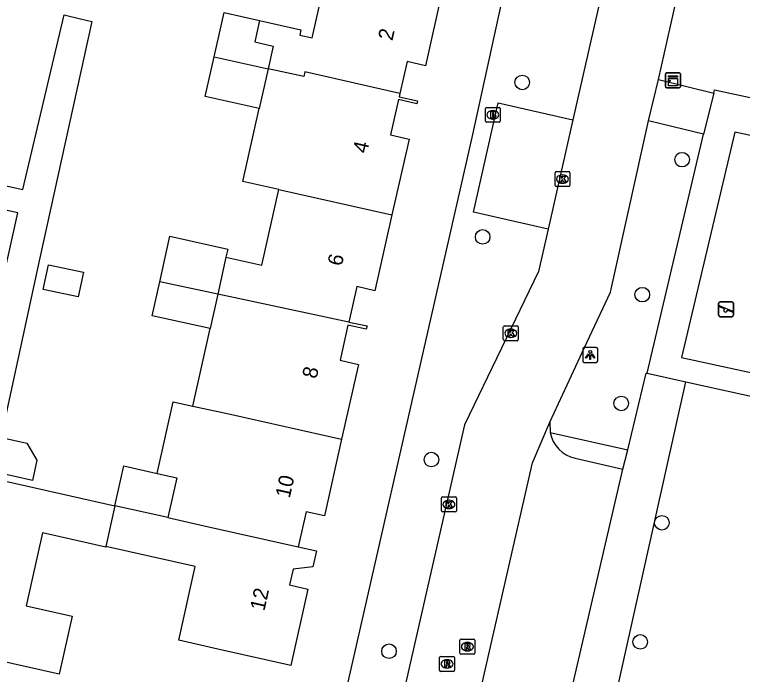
# Model space of a CAD drawing. Extents: x 163686 to 164493, y 382719 to 383870.
# Drawn here: x 164037.9 to 164086.64, y 383510.38 to 383554.53 of the extents above; entities that cross this region are included whole.
import ezdxf

# ---------------------------------------------------------------- set-up
doc = ezdxf.new("R2010")
doc.units = 0
for name, color, linetype in [('IMGEO_Boom', 7, 'Continuous'), ('IMGEO_Brandkraan', 7, 'Continuous'), ('IMGEO_Groenvoorziening', 7, 'Continuous'), ('IMGEO_Kast', 7, 'Continuous'), ('IMGEO_Kolk', 7, 'Continuous'), ('IMGEO_Lichtpunt', 7, 'Continuous'), ('IMGEO_Pand', 7, 'Continuous'), ('IMGEO_Pand_nummerreeks', 7, 'Continuous'), ('IMGEO_Parkeervlak_open', 7, 'Continuous'), ('IMGEO_Rijbaan_lokaal_open', 7, 'Continuous'), ('IMGEO_Rioolput', 7, 'Continuous'), ('IMGEO_Speelvoorziening', 7, 'Continuous'), ('IMGEO_Terreindeel_open', 7, 'Continuous'), ('IMGEO_Voetpad_open', 7, 'Continuous'), ('IMGEO_Woonerf_open', 7, 'Continuous')]:
    doc.layers.add(name, color=color, linetype=linetype)

msp = doc.modelspace()

# ---------------------------------------------------------------- linework, layer by layer
at = {"layer": 'IMGEO_Boom'}
for centre in [(164071.892, 383549.993), (164082.598, 383544.825), (164069.24, 383539.655), (164079.93, 383535.792), (164078.518, 383528.511), (164065.811, 383524.756), (164081.24, 383520.526), (164079.794, 383512.556), (164062.971, 383511.933)]:
    msp.add_circle(centre, 0.489, dxfattribs=at)
at = {"layer": 'IMGEO_Brandkraan'}
for p, q in [((164069.422, 383547.398), (164069.422, 383548.25)), ((164069.497, 383548.324), (164070.349, 383548.324)), ((164069.91, 383548.104), (164069.935, 383548.104)), ((164070.423, 383548.25), (164070.423, 383547.398)), ((164069.933, 383547.544), (164069.908, 383547.544)), ((164070.349, 383547.324), (164069.497, 383547.324))]:
    msp.add_line(p, q, dxfattribs=at)
for points in [[(164069.422, 383547.398), (164069.422, 383548.25)], [(164069.497, 383548.324), (164070.349, 383548.324)], [(164069.77, 383548.024), (164069.77, 383547.624), (164069.983, 383547.624)], [(164070.001, 383548.024), (164069.77, 383548.024)], [(164070.423, 383548.25), (164070.423, 383547.398)], [(164069.949, 383547.943), (164069.895, 383547.943), (164069.895, 383547.867)], [(164069.895, 383547.867), (164069.948, 383547.867)], [(164069.957, 383547.791), (164069.895, 383547.791), (164069.895, 383547.71)], [(164069.895, 383547.71), (164069.957, 383547.71)], [(164070.349, 383547.324), (164069.497, 383547.324)]]:
    msp.add_lwpolyline(points, dxfattribs=at)
for centre, radius, start, end in [((164069.499, 383548.248), 0.0765, 91.552, 178.448), ((164069.499, 383548.248), 0.0765, 91.552, 178.448), ((164070.005, 383547.879), 0.145, 59.4692, 91.5367), ((164070.03, 383547.926), 0.0922, 285.5137, 58.1501), ((164070.347, 383548.248), 0.0765, 1.552, 88.448), ((164070.347, 383548.248), 0.0765, 1.552, 88.448), ((164069.95, 383547.905), 0.0379, 267.8285, 90.9355), ((164069.958, 383547.75), 0.0404, 269.8759, 90.5077), ((164069.989, 383547.875), 0.251, 268.6676, 293.5347), ((164070.035, 383547.734), 0.105, 301.3115, 78.989), ((164069.499, 383547.4), 0.0765, 181.552, 268.448), ((164069.499, 383547.4), 0.0765, 181.552, 268.448), ((164070.347, 383547.4), 0.0765, 271.552, 358.448), ((164070.347, 383547.4), 0.0765, 271.552, 358.448)]:
    msp.add_arc(centre, radius, start, end, dxfattribs=at)
for centre, major_axis, ratio, start_param, end_param in [((164069.909, 383547.824), (-0.387, 0.002), 0.722429, 4.712389, 7.853982), ((164069.934, 383547.824), (-0.39, 0.002), 0.717154, 1.570796, 4.712389)]:
    msp.add_ellipse(centre, major_axis=major_axis, ratio=ratio, start_param=start_param, end_param=end_param, dxfattribs=at)
at = {"layer": 'IMGEO_Groenvoorziening'}
for points in [[(164084.714, 383549.273), (164084.769, 383549.493), (164114.437, 383543.108)], [(164080.248, 383530.541), (164084.032, 383546.541)], [(164078.964, 383525.408), (164080.184, 383530.549), (164080.248, 383530.541)], [(164080.248, 383530.541), (164082.853, 383529.966)], [(164068.968, 383467.759), (164082.853, 383529.966)], [(164082.853, 383529.966), (164127.033, 383520.232)]]:
    msp.add_lwpolyline(points, dxfattribs=at)
at = {"layer": 'IMGEO_Kast'}
for p, q in [((164081.483, 383549.714), (164081.483, 383550.555)), ((164081.483, 383550.555), (164081.483, 383549.714)), ((164081.558, 383550.639), (164082.399, 383550.639)), ((164082.399, 383550.639), (164081.558, 383550.639)), ((164082.483, 383550.564), (164082.483, 383549.723)), ((164082.483, 383549.723), (164082.483, 383550.564)), ((164082.408, 383549.639), (164081.567, 383549.639)), ((164081.567, 383549.639), (164082.408, 383549.639))]:
    msp.add_line(p, q, dxfattribs=at)
for points in [[(164081.678, 383550.429), (164082.278, 383550.429), (164082.278, 383550.344), (164081.678, 383550.344), (164081.678, 383550.429)], [(164081.678, 383550.254), (164082.278, 383550.254), (164082.278, 383549.765), (164081.678, 383549.765), (164081.678, 383550.254)]]:
    msp.add_lwpolyline(points, dxfattribs=at)
msp.add_circle((164081.762, 383550.103), 0.0377, dxfattribs=at)
for centre, start, end in [((164081.561, 383550.561), 92.4484, 184.2845), ((164081.561, 383550.561), 92.4484, 184.2845), ((164082.405, 383550.561), 2.4484, 94.2845), ((164082.405, 383550.561), 2.4484, 94.2845), ((164081.561, 383549.717), 182.4484, 274.2845), ((164081.561, 383549.717), 182.4484, 274.2845), ((164082.405, 383549.717), 272.4484, 4.2845), ((164082.405, 383549.717), 272.4484, 4.2845)]:
    msp.add_arc(centre, 0.0779, start, end, dxfattribs=at)
at = {"layer": 'IMGEO_Kolk'}
for p, q in [((164074.085, 383543.099), (164074.085, 383543.951)), ((164074.16, 383544.025), (164075.012, 383544.025)), ((164074.573, 383543.805), (164074.598, 383543.805)), ((164075.086, 383543.951), (164075.086, 383543.099)), ((164074.596, 383543.245), (164074.571, 383543.245)), ((164075.012, 383543.025), (164074.16, 383543.025)), ((164070.625, 383532.781), (164070.625, 383533.633)), ((164070.7, 383533.707), (164071.552, 383533.707)), ((164071.113, 383533.487), (164071.138, 383533.487)), ((164071.626, 383533.633), (164071.626, 383532.781)), ((164071.136, 383532.927), (164071.111, 383532.927)), ((164071.552, 383532.707), (164070.7, 383532.707)), ((164066.48, 383521.33), (164066.48, 383522.182)), ((164066.555, 383522.256), (164067.407, 383522.256)), ((164067.481, 383522.182), (164067.481, 383521.33)), ((164066.968, 383522.036), (164066.993, 383522.036)), ((164067.407, 383521.256), (164066.555, 383521.256)), ((164066.991, 383521.476), (164066.966, 383521.476))]:
    msp.add_line(p, q, dxfattribs=at)
for points in [[(164074.085, 383543.099), (164074.085, 383543.951)], [(164074.16, 383544.025), (164075.012, 383544.025)], [(164074.406, 383543.725), (164074.529, 383543.725), (164074.529, 383543.574), (164074.659, 383543.725), (164074.823, 383543.725), (164074.677, 383543.574), (164074.83, 383543.325), (164074.678, 383543.325), (164074.593, 383543.489), (164074.529, 383543.422), (164074.529, 383543.325), (164074.406, 383543.325), (164074.406, 383543.725)], [(164075.086, 383543.951), (164075.086, 383543.099)], [(164075.012, 383543.025), (164074.16, 383543.025)], [(164070.625, 383532.781), (164070.625, 383533.633)], [(164070.7, 383533.707), (164071.552, 383533.707)], [(164070.946, 383533.407), (164071.069, 383533.407), (164071.069, 383533.256), (164071.199, 383533.407), (164071.363, 383533.407), (164071.217, 383533.256), (164071.37, 383533.007), (164071.218, 383533.007), (164071.133, 383533.171), (164071.069, 383533.104), (164071.069, 383533.007), (164070.946, 383533.007), (164070.946, 383533.407)], [(164071.626, 383533.633), (164071.626, 383532.781)], [(164071.552, 383532.707), (164070.7, 383532.707)], [(164066.48, 383521.33), (164066.48, 383522.182)], [(164066.555, 383522.256), (164067.407, 383522.256)], [(164067.481, 383522.182), (164067.481, 383521.33)], [(164066.801, 383521.956), (164066.924, 383521.956), (164066.924, 383521.805), (164067.054, 383521.956), (164067.218, 383521.956), (164067.072, 383521.805), (164067.225, 383521.556), (164067.073, 383521.556), (164066.988, 383521.72), (164066.924, 383521.653), (164066.924, 383521.556), (164066.801, 383521.556), (164066.801, 383521.956)], [(164067.407, 383521.256), (164066.555, 383521.256)]]:
    msp.add_lwpolyline(points, dxfattribs=at)
for centre, start, end in [((164074.162, 383543.949), 91.552, 178.448), ((164074.162, 383543.949), 91.552, 178.448), ((164075.01, 383543.949), 1.552, 88.448), ((164075.01, 383543.949), 1.552, 88.448), ((164074.162, 383543.101), 181.552, 268.448), ((164074.162, 383543.101), 181.552, 268.448), ((164075.01, 383543.101), 271.552, 358.448), ((164075.01, 383543.101), 271.552, 358.448), ((164070.702, 383533.631), 91.552, 178.448), ((164070.702, 383533.631), 91.552, 178.448), ((164071.55, 383533.631), 1.552, 88.448), ((164071.55, 383533.631), 1.552, 88.448), ((164070.702, 383532.783), 181.552, 268.448), ((164070.702, 383532.783), 181.552, 268.448), ((164071.55, 383532.783), 271.552, 358.448), ((164071.55, 383532.783), 271.552, 358.448), ((164066.557, 383522.18), 91.552, 178.448), ((164066.557, 383522.18), 91.552, 178.448), ((164067.405, 383522.18), 1.552, 88.448), ((164067.405, 383522.18), 1.552, 88.448), ((164066.557, 383521.332), 181.552, 268.448), ((164066.557, 383521.332), 181.552, 268.448), ((164067.405, 383521.332), 271.552, 358.448), ((164067.405, 383521.332), 271.552, 358.448)]:
    msp.add_arc(centre, 0.0765, start, end, dxfattribs=at)
for centre, major_axis, ratio, start_param, end_param in [((164074.572, 383543.525), (-0.387, 0.002), 0.722429, 4.712389, 7.853982), ((164074.597, 383543.525), (-0.39, 0.002), 0.717154, 1.570796, 4.712389), ((164071.112, 383533.207), (-0.387, 0.002), 0.722429, 4.712389, 7.853982), ((164071.137, 383533.207), (-0.39, 0.002), 0.717154, 1.570796, 4.712389), ((164066.967, 383521.756), (-0.387, 0.002), 0.722429, 4.712389, 7.853982), ((164066.992, 383521.756), (-0.39, 0.002), 0.717154, 1.570796, 4.712389)]:
    msp.add_ellipse(centre, major_axis=major_axis, ratio=ratio, start_param=start_param, end_param=end_param, dxfattribs=at)
at = {"layer": 'IMGEO_Lichtpunt'}
for p, q in [((164075.947, 383532.16), (164075.947, 383531.353)), ((164075.947, 383532.16), (164075.947, 383531.353)), ((164076.849, 383532.255), (164076.041, 383532.255)), ((164076.849, 383532.255), (164076.041, 383532.255)), ((164076.943, 383531.353), (164076.943, 383532.16)), ((164076.943, 383531.353), (164076.943, 383532.16)), ((164076.041, 383531.259), (164076.849, 383531.259)), ((164076.041, 383531.259), (164076.849, 383531.259))]:
    msp.add_line(p, q, dxfattribs=at)
for points in [[(164076.321, 383531.824), (164076.36, 383531.796), (164076.172, 383531.534), (164076.134, 383531.561), (164076.321, 383531.824)], [(164076.423, 383531.776), (164076.47, 383531.776), (164076.47, 383531.454), (164076.423, 383531.454), (164076.423, 383531.776)], [(164076.533, 383531.796), (164076.571, 383531.823), (164076.758, 383531.561), (164076.719, 383531.533), (164076.533, 383531.796)]]:
    msp.add_lwpolyline(points, dxfattribs=at)
msp.add_circle((164076.446, 383531.958), 0.0994, dxfattribs=at)
for centre, start, end in [((164076.041, 383532.16), 90, 180), ((164076.041, 383532.16), 90, 180), ((164076.849, 383532.16), 0, 90), ((164076.849, 383532.16), 0, 90), ((164076.041, 383531.353), 180, 270), ((164076.041, 383531.353), 180, 270), ((164076.849, 383531.353), 270, 0), ((164076.849, 383531.353), 270, 360)]:
    msp.add_arc(centre, 0.0946, start, end, dxfattribs=at)
at = {"layer": 'IMGEO_Pand'}
for points in [[(164054.299, 383554.131), (164057.069, 383553.509), (164056.991, 383553.159), (164057.835, 383552.972), (164057.856, 383553.064), (164058.951, 383557.942), (164066.561, 383556.232), (164065.411, 383551.111), (164064.183, 383551.388), (164063.705, 383549.261)], [(164051.267, 383551.712), (164051.931, 383554.664), (164054.299, 383554.131)], [(164054.299, 383554.131), (164053.978, 383552.706), (164055.223, 383552.426), (164054.882, 383550.909)], [(164054.282, 383548.239), (164050.67, 383549.051), (164051.267, 383551.712)], [(164051.267, 383551.712), (164054.882, 383550.909)], [(164054.882, 383550.909), (164054.282, 383548.239)], [(164063.705, 383549.261), (164057.33, 383550.693), (164057.261, 383550.381), (164054.882, 383550.909)], [(164063.705, 383549.261), (164063.655, 383549.037), (164064.882, 383548.76), (164064.838, 383548.563), (164063.611, 383548.84), (164063.081, 383546.481), (164064.309, 383546.204), (164063.168, 383541.123)], [(164055.583, 383542.828), (164053.187, 383543.367), (164054.282, 383548.239)], [(164052.053, 383538.293), (164054.458, 383537.759), (164055.583, 383542.828)], [(164055.583, 383542.828), (164063.168, 383541.123)], [(164063.168, 383541.123), (164062.03, 383536.056), (164060.811, 383536.33), (164060.278, 383533.954)], [(164047.614, 383536.64), (164048.294, 383539.703), (164052.174, 383538.842), (164052.053, 383538.293)], [(164052.053, 383538.293), (164051.503, 383535.815)], [(164039.804, 383536.143), (164040.16, 383537.798), (164042.514, 383537.291), (164042.157, 383535.636), (164039.804, 383536.143)], [(164050.994, 383533.523), (164047.113, 383534.384), (164047.614, 383536.64)], [(164051.503, 383535.815), (164047.614, 383536.64)], [(164051.503, 383535.815), (164050.994, 383533.523)], [(164060.278, 383533.954), (164053.913, 383535.304), (164051.503, 383535.815)], [(164060.278, 383533.954), (164061.499, 383533.695), (164061.451, 383533.48), (164060.223, 383533.757), (164059.694, 383531.406), (164060.923, 383531.129), (164059.798, 383526.12)], [(164049.841, 383528.326), (164050.994, 383533.523)], [(164047.457, 383523.83), (164048.52, 383528.619), (164049.841, 383528.326)], [(164049.841, 383528.326), (164052.251, 383527.816), (164059.798, 383526.12)], [(164039.09, 383523.36), (164036.707, 383523.889), (164037.218, 383526.19), (164038.714, 383525.858), (164039.391, 383524.715), (164039.09, 383523.36)], [(164059.798, 383526.12), (164058.643, 383520.981), (164057.425, 383521.256), (164056.898, 383518.914)], [(164044.622, 383521.668), (164045.205, 383524.33), (164047.457, 383523.83)], [(164047.457, 383523.83), (164048.756, 383523.542), (164048.163, 383520.872)], [(164036.373, 383523.522), (164044.622, 383521.668)], [(164044.622, 383521.668), (164044.012, 383518.95)], [(164048.163, 383520.872), (164044.622, 383521.668)], [(164048.163, 383520.872), (164050.588, 383520.327), (164056.898, 383518.914)], [(164044.012, 383518.95), (164044, 383518.896), (164039.771, 383519.846), (164038.677, 383514.979), (164041.749, 383514.288), (164040.875, 383510.399), (164033.805, 383511.988)], [(164056.898, 383518.914), (164058.117, 383518.639), (164057.878, 383517.575), (164056.551, 383517.413), (164056.317, 383516.369), (164057.545, 383516.092), (164056.397, 383510.979), (164051.519, 383512.075), (164048.887, 383512.666), (164049.984, 383517.608), (164044.012, 383518.95)]]:
    msp.add_lwpolyline(points, dxfattribs=at)
at = {"layer": 'IMGEO_Parkeervlak_open'}
for points in [[(164069.055, 383509.1), (164072.57, 383524.545), (164073.749, 383527.249)], [(164073.749, 383527.249), (164073.764, 383526.569)], [(164075.24, 383509.499), (164078.623, 383524.109)]]:
    msp.add_lwpolyline(points, dxfattribs=at)
at = {"layer": 'IMGEO_Rijbaan_lokaal_open'}
for points in [[(164073.63, 383540.176), (164068.619, 383541.314), (164070.275, 383548.626), (164075.289, 383547.49)], [(164075.289, 383547.49), (164073.63, 383540.176)]]:
    msp.add_lwpolyline(points, dxfattribs=at)
at = {"layer": 'IMGEO_Rioolput'}
for p, q in [((164067.716, 383511.81), (164067.716, 383512.662)), ((164067.791, 383512.736), (164068.643, 383512.736)), ((164068.204, 383512.516), (164068.229, 383512.516)), ((164068.717, 383512.662), (164068.717, 383511.81)), ((164068.227, 383511.956), (164068.202, 383511.956)), ((164066.359, 383510.658), (164066.359, 383511.51)), ((164066.434, 383511.584), (164067.286, 383511.584)), ((164067.36, 383511.51), (164067.36, 383510.658)), ((164068.643, 383511.736), (164067.791, 383511.736)), ((164066.847, 383511.364), (164066.872, 383511.364)), ((164067.286, 383510.584), (164066.434, 383510.584)), ((164066.87, 383510.804), (164066.845, 383510.804))]:
    msp.add_line(p, q, dxfattribs=at)
for points in [[(164067.716, 383511.81), (164067.716, 383512.662)], [(164067.791, 383512.736), (164068.643, 383512.736)], [(164068.305, 383512.434), (164068.053, 383512.436), (164068.053, 383512.036)], [(164068.717, 383512.662), (164068.717, 383511.81)], [(164068.053, 383512.036), (164068.177, 383512.036), (164068.177, 383512.198), (164068.188, 383512.198)], [(164068.231, 383512.355), (164068.177, 383512.355), (164068.177, 383512.274)], [(164068.177, 383512.274), (164068.229, 383512.274)], [(164068.235, 383512.169), (164068.306, 383512.036), (164068.446, 383512.036), (164068.381, 383512.162)], [(164066.359, 383510.658), (164066.359, 383511.51)], [(164066.434, 383511.584), (164067.286, 383511.584)], [(164067.36, 383511.51), (164067.36, 383510.658)], [(164068.643, 383511.736), (164067.791, 383511.736)], [(164066.948, 383511.282), (164066.696, 383511.284), (164066.696, 383510.884)], [(164066.696, 383510.884), (164066.82, 383510.884), (164066.82, 383511.046), (164066.831, 383511.046)], [(164066.874, 383511.203), (164066.82, 383511.203), (164066.82, 383511.122)], [(164066.82, 383511.122), (164066.872, 383511.122)], [(164066.878, 383511.017), (164066.949, 383510.884), (164067.089, 383510.884), (164067.024, 383511.01)], [(164067.286, 383510.584), (164066.434, 383510.584)]]:
    msp.add_lwpolyline(points, dxfattribs=at)
for centre, radius, start, end in [((164067.793, 383512.66), 0.0765, 91.552, 178.448), ((164067.793, 383512.66), 0.0765, 91.552, 178.448), ((164068.304, 383512.324), 0.109, 350.3612, 89.416), ((164068.641, 383512.66), 0.0765, 1.552, 88.448), ((164068.641, 383512.66), 0.0765, 1.552, 88.448), ((164068.187, 383512.145), 0.0533, 26.0293, 88.6989), ((164068.213, 383512.463), 0.19, 274.7715, 282.9687), ((164068.237, 383512.259), 0.0964, 77.0061, 93.1865), ((164068.251, 383512.316), 0.0378, 276.6634, 79.6772), ((164068.302, 383512.324), 0.112, 277.5842, 350.9817), ((164068.286, 383512.109), 0.108, 29.5134, 73.7905), ((164066.436, 383511.508), 0.0765, 91.552, 178.448), ((164066.436, 383511.508), 0.0765, 91.552, 178.448), ((164067.284, 383511.508), 0.0765, 1.552, 88.448), ((164067.284, 383511.508), 0.0765, 1.552, 88.448), ((164067.793, 383511.812), 0.0765, 181.552, 268.448), ((164067.793, 383511.812), 0.0765, 181.552, 268.448), ((164068.641, 383511.812), 0.0765, 271.552, 358.448), ((164068.641, 383511.812), 0.0765, 271.552, 358.448), ((164066.83, 383510.993), 0.0533, 26.0293, 88.6989), ((164066.856, 383511.311), 0.19, 274.7715, 282.9687), ((164066.88, 383511.107), 0.0964, 77.0061, 93.1865), ((164066.894, 383511.164), 0.0378, 276.6634, 79.6772), ((164066.947, 383511.172), 0.109, 350.3612, 89.416), ((164066.945, 383511.172), 0.112, 277.5842, 350.9817), ((164066.929, 383510.957), 0.108, 29.5134, 73.7905), ((164066.436, 383510.66), 0.0765, 181.552, 268.448), ((164066.436, 383510.66), 0.0765, 181.552, 268.448), ((164067.284, 383510.66), 0.0765, 271.552, 358.448), ((164067.284, 383510.66), 0.0765, 271.552, 358.448)]:
    msp.add_arc(centre, radius, start, end, dxfattribs=at)
for centre, major_axis, ratio, start_param, end_param in [((164068.203, 383512.236), (-0.387, 0.002), 0.722429, 4.712389, 7.853982), ((164068.228, 383512.236), (-0.39, 0.002), 0.717154, 1.570796, 4.712389), ((164066.846, 383511.084), (-0.387, 0.002), 0.722429, 4.712389, 7.853982), ((164066.871, 383511.084), (-0.39, 0.002), 0.717154, 1.570796, 4.712389)]:
    msp.add_ellipse(centre, major_axis=major_axis, ratio=ratio, start_param=start_param, end_param=end_param, dxfattribs=at)
at = {"layer": 'IMGEO_Speelvoorziening'}
for p, q in [((164085.042, 383534.414), (164085.042, 383535.214)), ((164085.042, 383535.214), (164085.042, 383534.414)), ((164085.425, 383534.842), (164085.086, 383534.979)), ((164085.111, 383535.039), (164085.987, 383534.686)), ((164085.142, 383535.314), (164085.932, 383535.314)), ((164085.932, 383535.314), (164085.142, 383535.314)), ((164086.032, 383535.214), (164086.032, 383534.414)), ((164086.032, 383534.414), (164086.032, 383535.214)), ((164085.963, 383534.626), (164085.623, 383534.763)), ((164085.932, 383534.314), (164085.142, 383534.314)), ((164085.142, 383534.314), (164085.932, 383534.314))]:
    msp.add_line(p, q, dxfattribs=at)
for centre, radius, start, end in [((164085.142, 383535.214), 0.1, 90, 180), ((164085.142, 383535.214), 0.1, 90, 180), ((164085.099, 383535.009), 0.0327, 68.078, 248.078), ((164085.932, 383535.214), 0.1, 0, 90), ((164085.932, 383535.214), 0.1, 360, 90), ((164085.142, 383534.414), 0.1, 180, 270), ((164085.142, 383534.414), 0.1, 180, 270), ((164085.504, 383534.752), 0.12, 130.9928, 5.1632), ((164085.932, 383534.414), 0.1, 270, 0), ((164085.932, 383534.414), 0.1, 270, 0), ((164085.975, 383534.656), 0.0327, 248.078, 68.078)]:
    msp.add_arc(centre, radius, start, end, dxfattribs=at)
at = {"layer": 'IMGEO_Terreindeel_open'}
msp.add_lwpolyline([(164086.13, 383546.665), (164082.548, 383531.595), (164094.502, 383528.991), (164097.95, 383544.121), (164086.13, 383546.665)], dxfattribs=at)
at = {"layer": 'IMGEO_Voetpad_open'}
for points in [[(164079.551, 383566.268), (164078.316, 383560.83), (164075.289, 383547.49)], [(164047.857, 383454.839), (164051.208, 383470.304), (164068.531, 383546.311), (164072.003, 383562.118)], [(164035.485, 383543.472), (164038.456, 383542.817), (164041.21, 383554.506), (164042.305, 383554.248), (164043.082, 383554.065), (164039.552, 383538.055), (164036.373, 383523.522)], [(164080.349, 383547.423), (164081.005, 383550.183)], [(164081.005, 383550.183), (164084.714, 383549.273)], [(164084.714, 383549.273), (164084.032, 383546.541)], [(164084.032, 383546.541), (164081.264, 383547.204), (164080.349, 383547.423)], [(164028.068, 383496.176), (164032.229, 383514.859), (164038.113, 383541.275), (164028.338, 383543.43)], [(164073.63, 383540.176), (164072.988, 383537.346), (164068.033, 383527.084), (164059.009, 383487.507)], [(164073.764, 383526.569), (164078.964, 383525.408)], [(164078.623, 383524.109), (164078.964, 383525.408)], [(164075.428, 383524.845), (164078.623, 383524.109)]]:
    msp.add_lwpolyline(points, dxfattribs=at)
msp.add_arc((164075.883, 383526.949), 2.152, 190.1655, 257.8053, dxfattribs=at)
at = {"layer": 'IMGEO_Woonerf_open'}
for points in [[(164081.005, 383550.183), (164083.019, 383559.142)], [(164073.749, 383527.249), (164076.069, 383532.245), (164077.793, 383535.96), (164080.349, 383547.423)]]:
    msp.add_lwpolyline(points, dxfattribs=at)

# ---------------------------------------------------------------- texts
at = {"layer": 'IMGEO_Pand_nummerreeks'}
for s, p in [('2', (164063.195, 383552.742)), ('4', (164061.501, 383545.202)), ('6', (164059.807, 383537.66)), ('8', (164058.114, 383530.122)), ('10', (164056.318, 383522.13)), ('12', (164054.623, 383514.582))]:
    msp.add_text(s, height=1, rotation=77.3436, dxfattribs=at).set_placement(p)

doc.saveas('drawing.dxf')
